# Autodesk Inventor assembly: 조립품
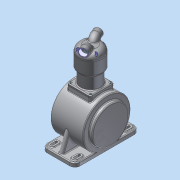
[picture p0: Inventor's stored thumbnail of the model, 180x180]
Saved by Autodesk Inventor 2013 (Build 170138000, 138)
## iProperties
Created: 2015-06
Part Number: 조립품
Document SubType Name: Assembly
Designer: Administrator
Author: Administrator
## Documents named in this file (5)
- C:\Users\Administrator\Desktop\450606V1012\조립품.iam
- C:\Users\Administrator\Desktop\450606V1012\본체.ipt
- C:\Users\Administrator\Desktop\450606V1012\실린더.ipt
- C:\Users\Administrator\Desktop\450606V1012\실린더헤드.ipt
- C:\Users\Administrator\Desktop\450606V1012\메인커버.ipt
